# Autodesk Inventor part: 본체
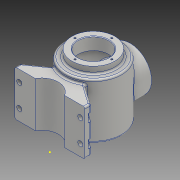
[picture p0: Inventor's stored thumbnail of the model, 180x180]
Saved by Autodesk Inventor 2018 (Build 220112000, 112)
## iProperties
Created: 2021-04
Part Number: 본체
Material: 알루미늄 6061
Document SubType Name: Modeling
Designer: home
Density: 2.7 g/cm^3
Appearance: 알루미늄 - 평지
Mass: 1641.59 g
Surface Area: 1039.47 cm^2
Volume: 607.998 cm^3
Author: home
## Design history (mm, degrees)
sketch "스케치1"
  geometry: L1 (0, 0)-(77, 0); L2 (127, 48)-(127, -48.336); L3 (127, 48)-(115, 48); L4 (115, 60)-(115, 48); L5 (115, 60)-(77, 60); L6 (77, 60)-(77, -60); L7 (104, 38)-(104, 60); L8 (117, 38)-(117, -41.916); L9 (104, 38)-(117, 38); A1 r 113 centre (77, 53) between (77, -60) and (127, -48.336); A2 r 103 centre (77, 53) between (77, -50) and (117, -41.916); 2 further points
  constraints: 18 end point, 4 point on circle, 3 horizontal, 2 centre point, 2 horizontal alignment, 2 perpendicular, 2 point on line, 2 vertical, 1 coincident, 1 midpoint, 1 parallel
  dimensions: "d6" = 77 distance of L1.start L1.end; "d7" = 113 radius of A1; "d12" = 120 distance of L5.end L6.end; "d22" = 40 distance between parallel lines of L6 L8; "d25" = 10 radial gap between concentric circles of A1 A2; "d124" = 100 diameter of L2 L6; "d125" = 12 distance between parallel lines of L4 L2; "d126" = 23 distance between parallel lines of L7 L2; "d127" = 10 distance between parallel lines of L9 L3; "d128" = 22 distance between parallel lines of L9 L5; "d129" = 86.33607 distance from line of L2.end L9; "d130" = 32.23748 distance from line of point (94.763, 0) L2
revolve "회전1" sketch "스케치1" stored, may be unused: angle "d40" = 90 deg
sketch "스케치2"
  geometry: L1 (62, 10)-(26.694, 34.722); L2 (-62, 10)-(-62, 0); L3 (62, 10)-(62, 0); L4 (0, 0)-(0, 15); L5 (-62, 0)-(-25.981, 0); L6 (25.981, 0)-(62, 0); L7 (-62, 10)-(-26.694, 34.722); A1 r 50 centre (0, 77) between (26.694, 34.722) and (-33.723, 40.084) reference; A2 r 30 centre (0, -15) between (25.981, 0) and (-25.981, 0); 2 further points
  constraints: 14 end point, 6 point on circle, 3 coincident, 2 horizontal, 2 perpendicular, 2 vertical, 1 centre point, 1 vertical alignment
  dimensions: "d41" = 124 distance of L2.end L3.end; "d48" = 15 distance of L4.start L4.end; "d115" = 55 deg angle of L3 L1; "d116" = 10 distance from line of L1.start L6; "d117" = 10 distance from line of L5 L2.start; "d118" = 55 deg angle of L2 L7; "d119" = 30 radius of A2; "d120" = 62 distance between parallel lines of L4 L3; "d121" = 124 distance between parallel lines of L3 L2; "d122" = 19.32145 distance from line of A1.centre L1; "d123" = 95.72285 distance from line of A1.end L3
extrude "돌출1" join sketch "스케치2" stored distance "d55" = 80; taper "d56" = 0 deg
node "작업 평면1"
sketch "스케치3"
  geometry: L1 (24, 20)-(100, 20) reference; C1 r 38 at (62, -42); 2 further points
  constraints: 1 centre point, 1 midpoint, 1 vertical alignment
  dimensions: "d60" = 38 radius of C1; "d61" = 62 distance from line of L1 C1.centre
extrude "돌출2" join sketch "스케치3" stored distance "d62" = 80; taper "d63" = 0 deg
sketch "스케치4"
  geometry: C1 r 38 at (0, 0) reference; C2 r 27 at (0, 0); 1 further point
  constraints: 1 centre point, 1 coincident
  dimensions: "d64" = 27 radius of C2
extrude "돌출3" cut sketch "스케치4" stored distance "d65" = 80; taper "d66" = 0 deg
sketch "스케치5"
  geometry: C1 r 40 at (0, 0) reference; 2 further points
  constraints: 1 vertical alignment
  dimensions: "d68" = 32.5 distance of C1.centre point (0, 32.5)
hole "구멍1" sketch "스케치5" at (0, 32.5) diameter "d69" = 3.242; stored, may be unused: countersink angle "d73" = 90 deg, drill point angle "d75" = 118 deg; dims "d70" = 8, "d71" = 4, "d72" = 2, "d74" = 10
sketch "스케치6"
  geometry: C1 r 27 at (0, 0) reference; C2 r 38 at (0, 0) reference; 2 further points
  constraints: 1 vertical alignment
  dimensions: "d80" = 32.5 distance of C1.centre point (0, 32.5)
hole "구멍2" sketch "스케치6" at (0, 32.5) diameter "d81" = 3.242; stored, may be unused: countersink angle "d85" = 90 deg, drill point angle "d87" = 118 deg; dims "d82" = 8, "d83" = 4, "d84" = 2, "d86" = 10
node "작업 평면3"
sketch "스케치9"
  geometry: L1 (36.019, 0)-(0, 0) reference; L2 (36.019, 0)-(36.019, 80) reference; L3 (28.019, 13)-(36.019, 13); L4 (28.019, 27)-(36.019, 27); A1 r 7 centre (28.019, 20) between (28.019, 13) and (28.019, 27); 1 further point
  constraints: 4 end point, 2 point on circle, 2 point on line, 1 centre point, 1 horizontal, 1 perpendicular, 1 tangent
  dimensions: "d99" = 7 radius of A1; "d100" = 20 distance from line of A1.centre L1; "d101" = 8 distance from line of A1.centre L2
extrude "돌출5" cut sketch "스케치9" distance "d102" = 20; taper "d103" = 0 deg
sketch "스케치10"
  geometry: L1 (28.019, -13)-(36.019, -13) reference; L2 (36.019, -27)-(28.019, -27) reference; L3 (36.019, -13)-(36.019, -27) reference; C1 r 4.5 at (28.019, -20); A1 r 7 centre (28.019, -20) between (28.019, -13) and (28.019, -27) reference; 1 further point
  constraints: 1 centre point, 1 coincident
  dimensions: "d104" = 4.5 radius of C1
extrude "돌출6" cut sketch "스케치10" extent not by distance; stored distance "d105" = 20; taper "d106" = 0 deg
node "작업 평면4"
sketch "스케치11"
  geometry: 1 further point
chamfer "모따기1" distance "d111" = 1; stored, may be unused: second distance "d112" = 2, angle "d113" = 45 deg
fillet "모깎기1" dims "d114" = 3
node "작업 평면5"
sketch "스케치13"
  geometry: C1 r 48.282 at (0, 0) reference; 2 further points
  constraints: 2 coincident, 1 other
feature "엠보싱1" sketch "스케치13" dims "d41" = 124, "d48" = 15, "d115" = 55 deg, "d116" = 10, "d117" = 10, "d118" = 55 deg, "d119" = 30, "d120" = 62, "d121" = 124, "d122" = 19.32145, "d123" = 95.72285, "d131" = 0.5, "d132" = 0
node "솔리드1"
pattern_circular "원형 패턴1" dims angle "d77" = 360 deg
pattern_circular "원형 패턴2" dims angle "d89" = 360 deg
pattern_linear "직사각형 패턴1" dims "d109" = 40
mirror "미러1"
node "투영된 루프1"
node "투영된 루프2"
node "투영된 루프3"
node "투영된 루프5"
node "투영된 루프6"
other parameters: "d43" = 45 deg, "d44" = 45 deg, "d57" = -142, "d98" = -6, "d110" = -108
